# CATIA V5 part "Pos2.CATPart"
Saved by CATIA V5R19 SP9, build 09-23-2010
Part number: Pos2
Bounding box of the stored display mesh (mm): x 0 to 1500, y -25 to 25, z -50 to 50
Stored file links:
  D:\UG\Beispiel\R19\Produkt_ZSB\Pos2.CATPart
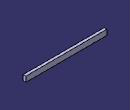
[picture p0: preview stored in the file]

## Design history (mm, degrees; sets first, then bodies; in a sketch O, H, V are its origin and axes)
AxisSystem1: origin (0, 0, 0), X (1, 0, 0), Y (0, 1, 0), Z (0, 0, 1)
Body1 (main body)
  Sketch1 on YZ plane of AxisSystem1, origin (0, 0, 0), H (0, 1, 0), V (0, 0, 1)
    line L1 (-25, 50) -> (25, 50)
    line L2 (25, 50) -> (25, -50)
    line L3 (25, -50) -> (-25, -50)
    line L4 (-25, -50) -> (-25, 50)
    distance L1 L3 = 100
    length L3 = 50
    horizontal: L1 H, L3 H
    vertical: L2 V, L4 V
    symmetry: L4 L2 V, L1 L3 H
  Pad1: profile Sketch1, direction (1, 0, 0), length 1500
